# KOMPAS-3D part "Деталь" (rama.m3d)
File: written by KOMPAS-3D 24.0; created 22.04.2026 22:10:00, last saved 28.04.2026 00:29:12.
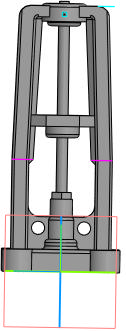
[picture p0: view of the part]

Document properties: Автор: mrdid; Полное имя файла: C:\Работа\ГОТОВЫЕ ИСХОДНИКИ\VSO2130M-F-S Клапан запорный сильфонный DN.ru Ду15-100 Ру40\исходные материалы\DN15\rama.m3d

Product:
- Part/product: Деталь
    Масса: 0.451515

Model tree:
1. Эскиз:2
2. Элемент выдавливания:1
     Расстояние 1 = 10
3. Эскиз:3  (with: Грань.Элемент выдавливания:1, Ребро.Элемент выдавливания:1)
4. Элемент выдавливания:2
     Расстояние 2 = 10
5. Массив по сетке:1  (with: Элемент выдавливания:2, Эскиз:3)  (4 pattern instances)
     Угол раствора = 90
6. Эскиз:4  (with: Грань.Элемент выдавливания:1)
7. Элемент выдавливания:3
     Расстояние 1 = 4.5
8. Эскиз:5  (with: Грань.Элемент выдавливания:3, Ребро.Элемент выдавливания:3)
9. Элемент выдавливания:4
     Расстояние 1 = 10
10. Эскиз:6  (with: Грань.Элемент выдавливания:1, Ребро.Элемент выдавливания:1)
11. Элемент выдавливания:5
     Расстояние 1 = 40
12. Эскиз:23  (with: Грань.Элемент выдавливания:4, Ребро.Элемент выдавливания:4)
13. Элемент выдавливания:21
     Расстояние 1 = 11
14. Эскиз:7  (with: Грань.Элемент выдавливания:21, Ребро.Элемент выдавливания:3)
15. Элемент выдавливания:6
     Расстояние 2 = 3
16. Эскиз:8  (with: Грань.Элемент выдавливания:5, Ребро.Элемент выдавливания:5)
17. Смещенная плоскость:1  (with: Грань.Элемент выдавливания:5)
18. Эскиз:9
19. Элемент по сечениям:1
20. Элемент по сечениям:2
21. Эскиз:10
22. Элемент выдавливания:8
     Расстояние 2 = 5
23. Эскиз:11  (with: Грань.Элемент выдавливания:8, Ребро.Элемент выдавливания:3)
24. Элемент выдавливания:9  (with: Грань.Элемент выдавливания:8)
     Расстояние 1 = 1; Расстояние 2 = 7; Смещение 2 = 2
25. Эскиз:12  (with: Грань.Элемент выдавливания:9, Ребро.Элемент выдавливания:9)
26. Элемент выдавливания:10
     Расстояние 1 = 2
27. Эскиз:13  (with: Грань.Элемент выдавливания:21, Ребро.Элемент выдавливания:3)
28. Элемент выдавливания:11  (with: Грань.Элемент выдавливания:10)
     Расстояние 1 = 74.488
29. Смещенная плоскость:2  (with: Грань.Элемент выдавливания:21)
30. Эскиз:14  (with: Ребро.Элемент по сечениям:2, Ребро.Элемент по сечениям:1)
31. Элемент выдавливания:12
     Расстояние 1 = 5
32. Эскиз:15  (with: Грань.Элемент выдавливания:12, Ребро.Элемент выдавливания:3)
33. Элемент выдавливания:13
     Расстояние 1 = 5
34. Эскиз:16  (with: Ребро.Элемент выдавливания:5, Ребро.Элемент выдавливания:1, Ребро.Элемент выдавливания:4)
35. Элемент выдавливания:14
     Расстояние 1 = 4
36. Элемент выдавливания:15
     Расстояние 1 = 2
37. Эскиз:17  (with: Ребро.Элемент выдавливания:5, Ребро.Элемент выдавливания:14)
38. Элемент выдавливания:16
     Расстояние 1 = 26.5; Расстояние 2 = 26.5
39. Скругление:1  (with: Ребро.Элемент выдавливания:1, Ребро.Элемент выдавливания:3)
     Радиус = 1.5
40. Скругление:2  (with: Ребро.Элемент выдавливания:9, Ребро.Элемент выдавливания:10, Ребро.Элемент выдавливания:13, Ребро.Элемент выдавливания:4)
41. Эскиз:18  (with: Грань.Элемент выдавливания:9)
42. Элемент выдавливания:17
     Расстояние 1 = 1
43. Скругление:3  (with: Ребро.Элемент по сечениям:2, Ребро.Элемент по сечениям:1)
     Радиус = 5
44. Скругление:4  (with: Ребро.Элемент выдавливания:8)
     Радиус = 1
45. Скругление:5  (with: Ребро.Элемент выдавливания:14)
     Радиус = 5
46. Эскиз:19  (with: Ребро.Элемент выдавливания:17, Ребро.Скругление:2, Ребро.Элемент выдавливания:9)
47. Элемент выдавливания:18
48. Смещенная плоскость:3  (with: Грань.Элемент выдавливания:18)
     Расстояние = 2
49. Эскиз:20  (with: Ребро.Элемент выдавливания:18)
50. Элемент выдавливания:19
     Расстояние 2 = 0.2
51. Скругление:6  (with: Ребро.Элемент выдавливания:18)
     Радиус = 1
52. Эскиз:21  (with: Ребро.Элемент выдавливания:19)
53. Элемент выдавливания:20
     Расстояние 1 = 10
54. Скругление:7  (with: Ребро.Элемент по сечениям:2, Ребро.Элемент выдавливания:5, Ребро.Элемент по сечениям:1)
     Радиус = 1
55. Фаска:1  (with: Ребро.Элемент по сечениям:1, Ребро.Элемент по сечениям:2)
     Угол = 45; Длина 1 = 2; Длина 2 = 2

Expressions: v249/2; D2/2-3; D2-3*2; DN/2
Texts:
  DN+5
